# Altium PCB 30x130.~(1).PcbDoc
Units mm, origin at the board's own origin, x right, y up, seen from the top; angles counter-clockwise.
Board outline 127 x 31.6 mm, 4 copper layers (Top Layer, Internal Plane 1, Internal Plane 2, Bottom Layer); 12 components, 8 nets, 22 pads, 0 vias.
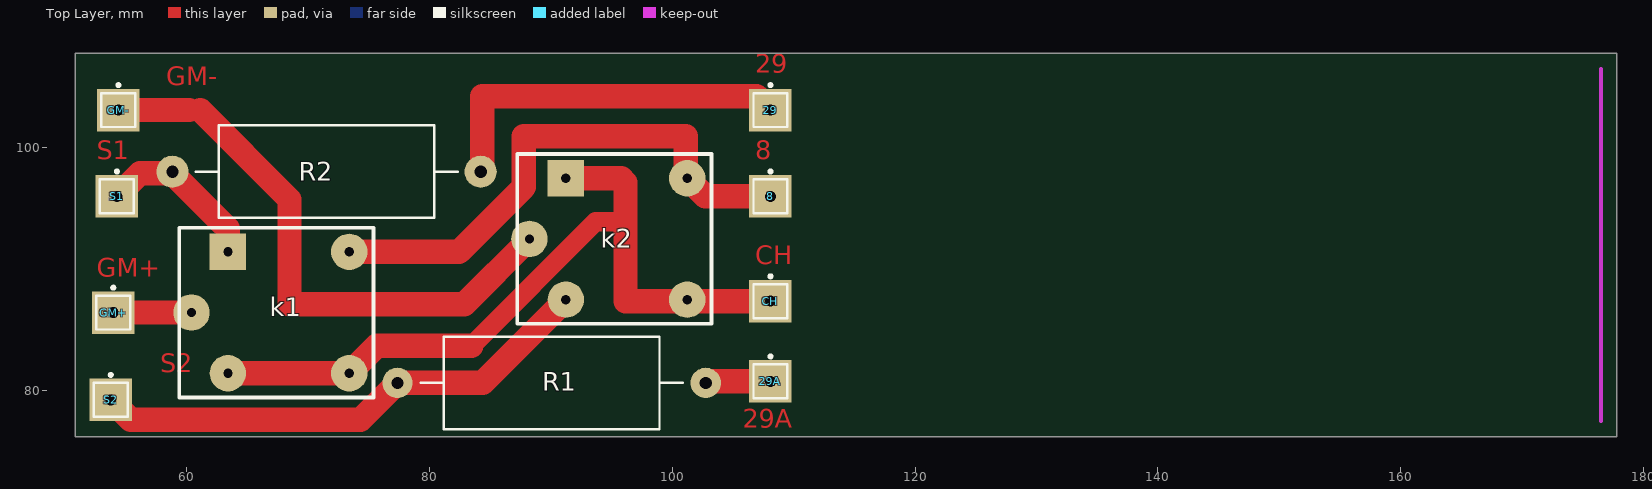
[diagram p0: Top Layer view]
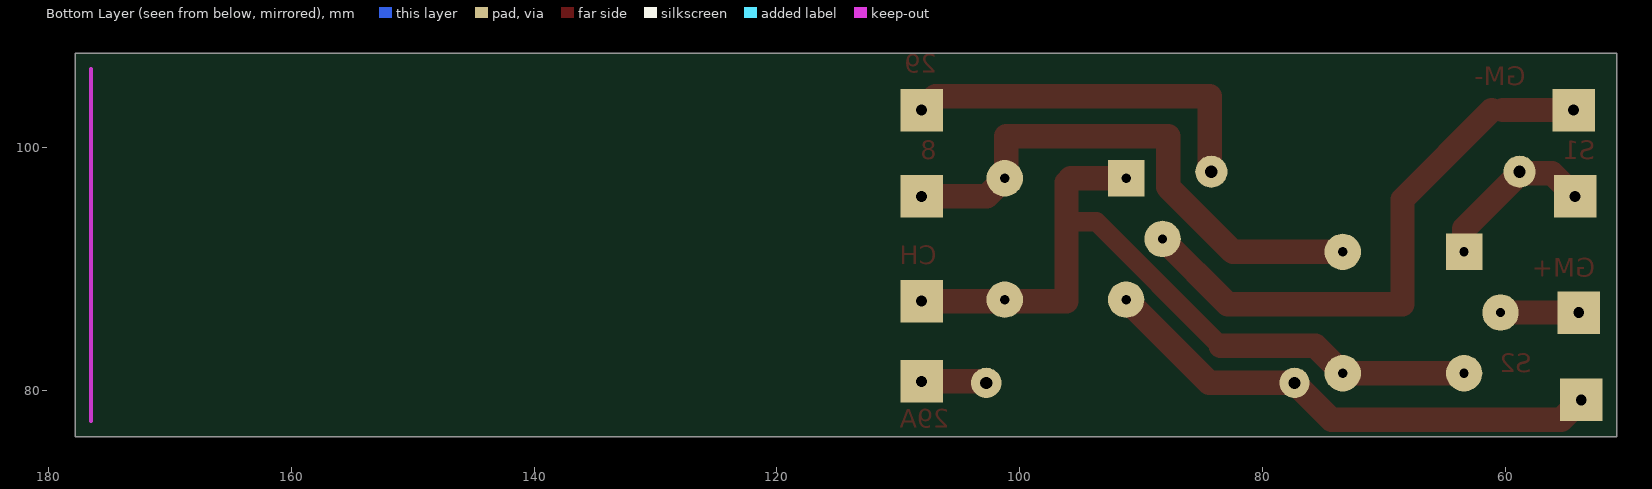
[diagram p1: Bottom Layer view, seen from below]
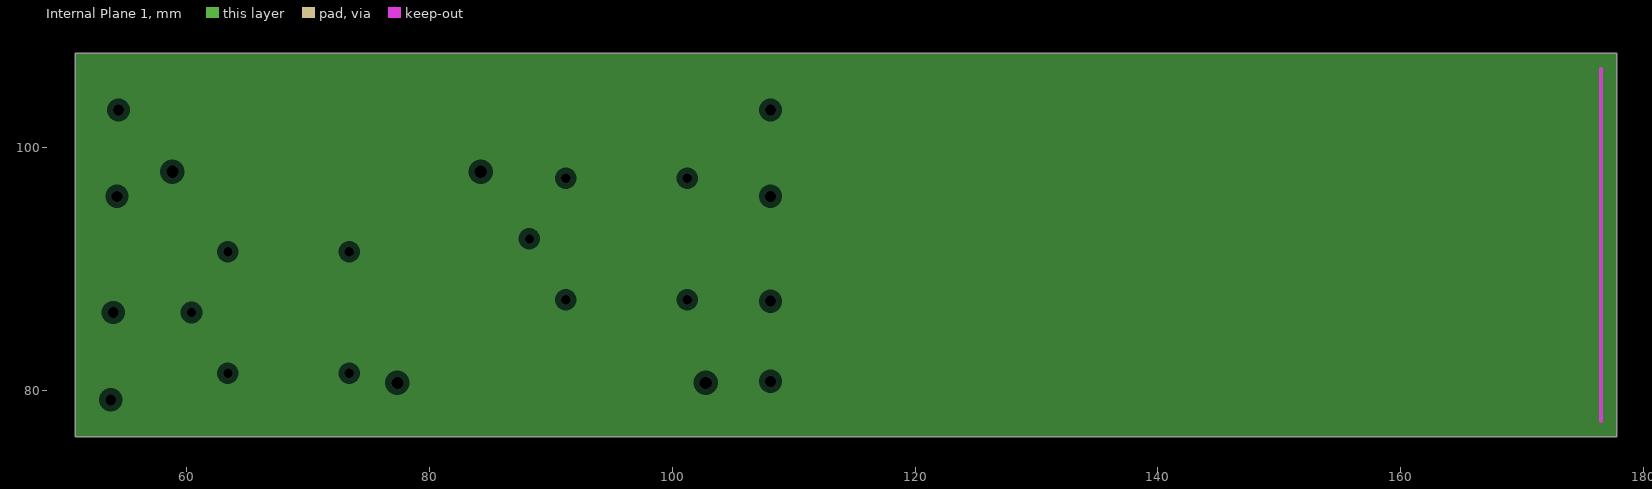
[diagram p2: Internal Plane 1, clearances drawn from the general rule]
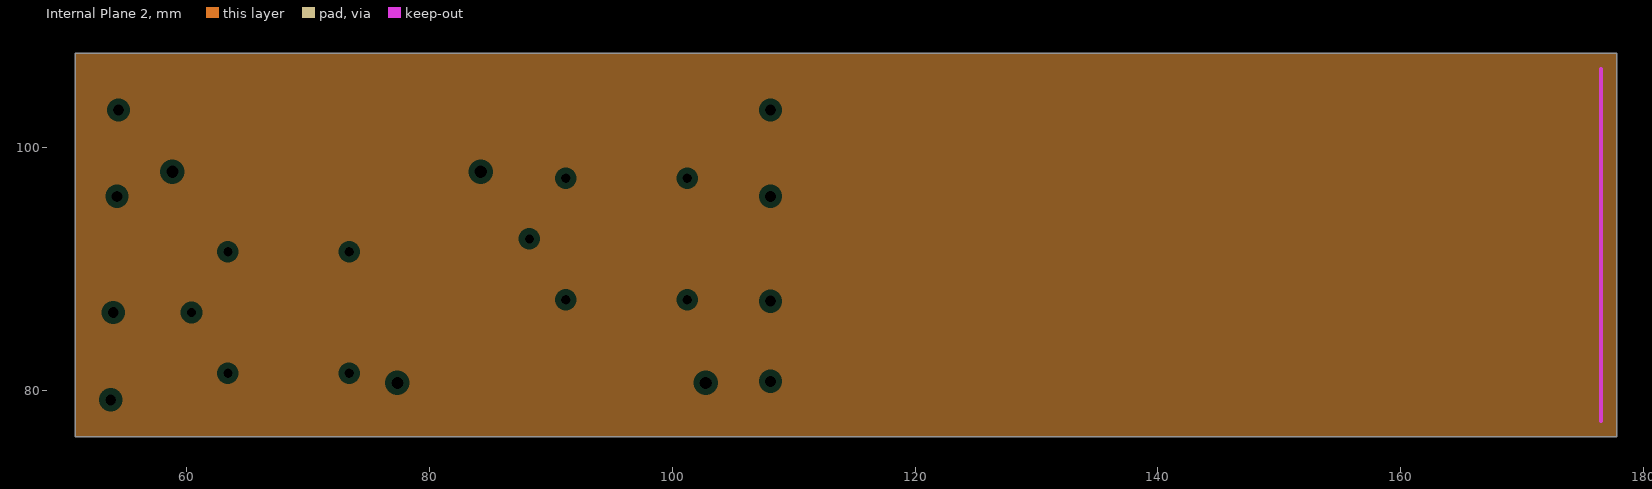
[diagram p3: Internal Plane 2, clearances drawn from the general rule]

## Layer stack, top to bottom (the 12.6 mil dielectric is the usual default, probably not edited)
Top Layer: signal copper 0.0356
Dielectric: dielectric 0.32, FR-4, Dk 4.8
Internal Plane 1: plane copper 0.0356
Dielectric: dielectric 0.32, FR-4, Dk 4.8
Internal Plane 2: plane copper 0.0356
Dielectric: dielectric 0.32, FR-4, Dk 4.8
Bottom Layer: signal copper 0.0356

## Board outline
50.8,76.2 177.8,76.2 177.8,107.8 50.8,107.8

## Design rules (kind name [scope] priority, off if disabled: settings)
Clearance [All] p1: gap=0.5
PlaneClearance [All] p1: clearance=0.508
PlaneConnect [All] p1: planeconnectstyle=Relief reliefexpansion=0.508 reliefentries=4 reliefconductorwidth=0.254 reliefairgap=0.254
PolygonConnect [All] p1: connectstyle=Relief reliefconductorwidth=0.254 reliefentries=4 polygonreliefangle="90 Angle"
RoomDefinition Sheet1 [InComponentClass('Sheet1')] p1: confinementstyle=ConfineIn formatcopy=TRUE lockcomponents=FALSE outline 51.943,76.581 139.7,76.581 139.7,106.807 51.943,106.807
RoutingVias [All] p1: holewidth=2 width=2 viastyle="Through Hole" minholewidth=0.711 minwidth=1.27 maxholewidth=3.711 maxwidth=3.27
SolderMaskExpansion [All] p1: expansion=0.102
TestPointUsage [All] p1: valid=0 allowmultiple=FALSE
Testpoint [All] p1: side=15 testpointundercomponent=TRUE minsize=1.016 maxsize=2.54 preferedsize=1.524 minholesize=0 maxholesize=1.016 preferedholesize=0.813 testpointgrid=0.025 style=1023 order=0123456789
Width [All] p1: maxlimit=4 minlimit=0.8 preferedwidth=0.8 minimp=50.000000 maximp=50.000000 favimp=50.000000
17 further rules are at their usual default settings.

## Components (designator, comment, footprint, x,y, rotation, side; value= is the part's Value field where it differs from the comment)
8 "8" PIN1 108.077,96.012 r0 top (schematic designator P3)
29 "29A" PIN1 108.077,103.124 r0 top (schematic designator P1)
29A "29" PIN1 108.077,80.772 r0 top (schematic designator P2)
CH "CH" PIN1 108.077,87.376 r0 top (schematic designator P4)
GM+ "Motor" PIN1 53.929,86.44 r0 top (schematic designator P5)
GM- "Motor" PIN1 54.356,103.124 r0 top (schematic designator P6)
k1 "Component_1" PCBComponent_1 56.373,78.44 r0 top
k2 "Component_1" PCBComponent_1 84.219,84.503 r0 top
R1 "Res2" AXIAL-1.0#1 90.043,80.645 r180 top
R2 "Res2" AXIAL-1.0#2 71.501,98.044 r180 top
S1 "S1" PIN1 54.229,96.012 r0 top (schematic designator P7)
S2 "S2" PIN1 53.721,79.248 r0 top (schematic designator P8)

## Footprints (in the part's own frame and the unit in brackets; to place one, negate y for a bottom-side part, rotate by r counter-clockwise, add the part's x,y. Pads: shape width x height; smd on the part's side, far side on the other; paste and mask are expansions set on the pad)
AXIAL-1.0#1 [mm] "Adjustable Magnetic-Core Inductor; 2 Leads"
  round 2.5 hole 1: 1(-12.7,0) 2(12.7,0)
  silkscreen extent -10.79,-3.81 10.79,3.81
AXIAL-1.0#2 [mm] "Adjustable Magnetic-Core Inductor; 2 Leads"
  round 2.65 hole 1: 1(-12.7,0) 2(12.7,0)
  silkscreen extent -10.79,-3.81 10.79,3.81
PCBComponent_1 [mm]
  rect 3x3 hole 0.762: 1(7,13)
  round 3 hole 0.762: 2(7,3) 3(4,8) 4(17,13) 5(17,3)
  silkscreen extent 3,1 19,15, body extent 3,1 19,15, height 12.5
PIN1 [mm] "Connector; Plug"
  rect 3.5x3.5 hole 0.9: 1(0,0)
  silkscreen extent -1.4,-1.4 1.4,2.17

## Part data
8 29 29A CH GM+ GM- S1 S2: library part Plug, "Plug"
R1 R2: "Resistor"

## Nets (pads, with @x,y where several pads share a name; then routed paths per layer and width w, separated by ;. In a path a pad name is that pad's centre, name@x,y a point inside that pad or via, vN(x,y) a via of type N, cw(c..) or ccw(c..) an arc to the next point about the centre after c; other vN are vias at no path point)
GND: CH.1 k1.2 k1.5 k2.1 k2.5 | length 64.7
  Top Layer w1.6: 83.439,83.693 93.662,93.916 96.139,93.916
  Top Layer w2: k1.2 k1.5 75.626,83.693 83.439,83.693 ; k2.1 95.791,97.503 96.139,97.155 96.139,93.916 96.139,87.376 101.219,87.376 CH.1
Netk1_1: k1.1 R2.2 S1.1 | length 13.7
  Top Layer w2: S1.1 56.134,97.917 58.801,97.917 63.373,93.345 k1.1
Netk1_3: GM+.1 k1.3 | length 6.4
  Top Layer w2: GM+.1 k1.3
Netk1_4: 8.1 k1.4 k2.4 | length 45.1
  Top Layer w2: k1.4 82.423,91.44 87.757,96.774 87.757,100.965 101.092,100.965 101.092,97.63 k2.4 102.71,96.012 8.1
Netk2_2: k2.2 R1.2 S2.1 | length 42.4
  Top Layer w2: S2.1 55.372,77.597 74.295,77.597 R1.2 ; k2.2 84.361,80.645 R1.2 ; R1.2 77.376,80.678 R1.2
Netk2_3: GM-.1 k2.3 | length 46.9
  Top Layer w2: GM-.1 60.198,103.124 ; 61.087,103.124 68.453,95.758 68.453,87.122 82.838,87.122 k2.3
NetP1_1: 29.1 R2.1 | length 30.5
  Top Layer w2: R2.1 84.328,98.171 84.328,104.267 106.934,104.267 29.1
NetP2_1: 29A.1 R1.1 | length 5.2
  Top Layer w2: R1.1@102.87,80.772 29A.1

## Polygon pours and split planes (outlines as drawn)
no net on Internal Plane 1 (split plane): 177.8,76.2 50.8,76.2 50.8,107.8 177.8,107.8
no net on Internal Plane 2 (split plane): 177.8,76.2 50.8,76.2 50.8,107.8 177.8,107.8

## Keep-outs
Keep-Out Layer:
  lines w0.3: 176.5,77.5 176.5,106.5

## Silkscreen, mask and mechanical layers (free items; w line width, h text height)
Drill Drawing:
  text ".LEGEND" at 182.88,81.28 h1.52
  text "Drill Drawing." at 182.88,78.74 h1.52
